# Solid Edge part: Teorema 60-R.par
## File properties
Title: Terorema 60/R
Author: DESYS
Template: Normal.par
Last saved by: s.pallini
Revision: 16
Application: Solid Edge
Tipo di contenuto documento: 0
Precisione: 0,990
Document Number: 8031/R 60
Revision: 0
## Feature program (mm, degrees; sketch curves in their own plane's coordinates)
sketch for "unnamed Protrusion 1" plane through (0, 0, 0) normal (0, 0, 1) x-axis (1, 0, 0)
  line (-230, -300) -> (230, -300)
  line (230, -300) -> (230, 300)
  line (230, 300) -> (-230, 300)
  line (-230, 300) -> (-230, -300)
  dimension (linear) = 230
  dimension (linear) = 230
extrude "unnamed Protrusion 1" add finite 140 along +normal
lofted cutout "unnamed LoftedCutout 1"
sketch for "ExtrudedCutout_6" plane through (-100, 0, 0) normal (1, 0, 0) x-axis (0, 1, 0)
  line (288, 0) -> (285.675, 12)
  line (285.675, 12) -> (-285.675, 12)
  line (-288, 0) -> (-285.675, 12)
  line (288, 0) -> (-288, 0)
extrude "ExtrudedCutout_6" cut finite 119 along -normal
sketch for "ExtrudedCutout_2" plane through (0, 0, 140) normal (0, 0, 1) x-axis (0, 1, 0)
  line (-210, -135) -> (210, -135)
  arc centre (210, -120) radius 15 from (210, -135) to (225, -120) ccw
  line (225, -120) -> (225, 197.6571)
  line (-225, 197.6571) -> (225, 197.6571)
  line (-225, 197.6571) -> (-225, -120)
  arc centre (-210, -120) radius 15 from (-225, -120) to (-210, -135) ccw
  dimension (linear) = 225
extrude "ExtrudedCutout_2" cut finite 40 along -normal  Treatment1_DraftAngle = 10 deg
sketch for "Scavo3" plane through (0, 0, 140) normal (0, 0, 1) x-axis (0, -1, 0)
  line (-137.5, -200) -> (137.5, -200)
  arc centre (137.5, -185) radius 15 from (137.5, -200) to (152.5, -185) ccw
  line (152.5, -185) -> (152.5, -115)
  arc centre (137.5, -115) radius 15 from (137.5, -100) to (152.5, -115) cw
  line (137.5, -100) -> (-137.5, -100)
  arc centre (-137.5, -115) radius 15 from (-152.5, -115) to (-137.5, -100) cw
  line (-152.5, -115) -> (-152.5, -185)
  arc centre (-137.5, -185) radius 15 from (-152.5, -185) to (-137.5, -200) ccw
  dimension (linear) = 137.5
extrude "Scavo3" cut finite 115 along -normal  Treatment1_DraftAngle = 10 deg
draft "Draft_1"  Angles1 = 10 deg
sketch for "ExtrudedProtrusion_2" plane through (0, 0, 100) normal (0, 0, 1) x-axis (0, -1, 0)
  circle centre (-0.0692, 30) radius 35
extrude "ExtrudedProtrusion_2" add finite 40 along +normal
sketch for "ExtrudedProtrusion_3" plane through (0, 0, 0) normal (0, -1, 0) x-axis (1, 0, 0)
  line (5.5887, 130.8081) -> (-103.3048, 130.8081)
  line (5.5887, 100) -> (5.5887, 130.8081)
  line (-107.0531, 100) -> (5.5887, 100)
  line (-120.2776, 25) -> (-107.0531, 100)
  line (-142.9391, 25) -> (-120.2776, 25)
  line (-127.925, 110.1493) -> (-142.9391, 25)
  arc centre (-103.3048, 105.8081) radius 25 from (-127.925, 110.1493) to (-103.3048, 130.8081) cw
extrude "ExtrudedProtrusion_3" add finite 45 symmetric
sketch for "Foro_1" plane through (12.5, 0.0692, 140) normal (0, 0, 1) x-axis (0, -1, 0)
  hole centre (0, 17.5) bore radius 25
hole "Foro_1" diameter 50 through
sketch for "Foro_2" plane through (-100, 0, 46) normal (1, 0, 0) x-axis (0, -1, 0)
  hole centre (0, 4) bore radius 10
hole "Foro_2" diameter 20 finite
fillet "Rotondo_7" radius 5
fillet "Rotondo_14" radius 5
fillet "Rotondo_17" radius 15
fillet "Rotondo_18" radius 6
fillet "Rotondo_19" radius 6
fillet "Rotondo_20" radius 6
sketch for "Foro_4" plane through (-155, 0, 12) normal (0, 0, -1) x-axis (0, -1, 0)
  hole centre (0, 5) bore radius 18
hole "Foro_4" diameter 36 through
fillet "Rotondo_21" radius 15
fillet "Rotondo_22" radius 5
fillet "Rotondo_23" radius 5
fillet "Rotondo_24" radius 5
fillet "Rotondo_25" radius 5
sketch for "Foro_5" plane through (-230, 0, 50) normal (-1, 0, 0) x-axis (0, -1, 0)
  hole centre (-278, 68) bore radius 8
hole "Foro_5" finite
fillet "Rotondo_26" radius 6
sketch for "ExtrudedCutout_7" plane through (-230, 0, 72.5) normal (-1, 0, 0) x-axis (0, 1, 0)
extrude "ExtrudedCutout_7" cut finite 60 along -normal
sketch for "unnamed Cutout 1" #1 plane through (-230, 0, 72.5) normal (-1, 0, 0) x-axis (0, 1, 0)
  line (120, 12.5) -> (110, 12.5)
  arc centre (110, 22.5) radius 10 from (110, 12.5) to (110, 32.5) cw
  line (110, 32.5) -> (120, 32.5)
  arc centre (120, 22.5) radius 10 from (120, 12.5) to (120, 32.5) ccw
sketch for "unnamed Cutout 1" #2 plane through (-230, 0, 72.5) normal (-1, 0, 0) x-axis (0, 1, 0)
  line (-120, 12.5) -> (-110, 12.5)
  line (-110, 32.5) -> (-120, 32.5)
  dimension (linear) = 110
  dimension (linear) = 110
extrude "unnamed Cutout 1" cut through along -normal
fillet "Rotondo_27" radius 5
fillet "Rotondo_28" radius 5
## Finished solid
Body 1: solid body, 179 faces, 417 edges, 238 vertices.
  Faces by surface: cylinder 71, plane 37, blend 33, torus 20, sphere 10, cone 6, swept 2
  Edges by curve: line 165, circle 151, ellipse 50, intersection 49, spline 2
Bounding box of the edges (mm; curved faces can reach further): 460.000 x 600.000 x 140.000, from (-230, -300, 0) to (230, 300, 140).
Cylindrical faces by radius (mm): R5 x41, R6 x14, R8 x1, R10 x5, R15 x4, R18 x1, R25 x4, R35 x1
Conical faces (half-angle, radius in mm at the cone's reference point): 10 deg R15 x6
Toroidal faces (ring radius, tube radius in mm): R1 r5 x4, R3.7514 r5 x2, R10 r5 x2, R12.1424 r5 x4, R19.1955 r5 x2, R20 r5 x2, R23 r5 x1, R30 r5 x1, R40 r5 x1, R40 r15 x1
Spherical faces by radius (mm): R5 x10
Planar faces by outward normal: +x 3, +y 2, +z 9, -x 2, -y 2, -z 5, oblique 14
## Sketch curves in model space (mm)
line (198, -272.5, 80) -> (-100, -272.5, 80)
line (-100, -272.5, 80) -> (-100, 272.5, 80)
line (-100, 272.5, 80) -> (198, 272.5, 80)
line (198, 272.5, 80) -> (198, -272.5, 80)
line (218, -288, 0) -> (-100, -288, 0)
line (-100, -288, 0) -> (-100, 288, 0)
line (-100, 288, 0) -> (218, 288, 0)
line (218, 288, 0) -> (218, -288, 0)
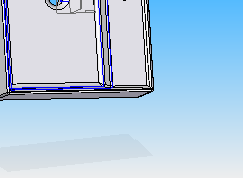
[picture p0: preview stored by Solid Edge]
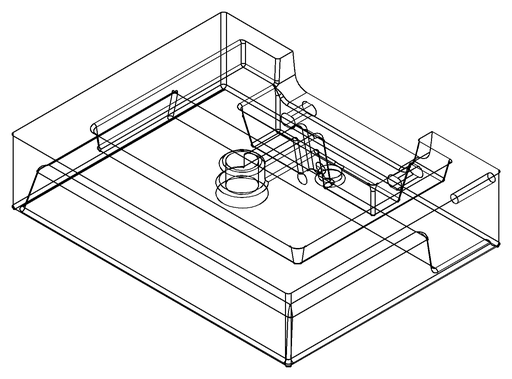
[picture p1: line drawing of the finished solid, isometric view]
